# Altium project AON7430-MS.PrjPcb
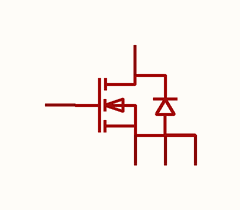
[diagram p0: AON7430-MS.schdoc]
1 sheet, 1 parts. Net scope: global (net labels, ports and power ports of the same name join across sheets).

## Sheet AON7430-MS.schdoc
size 127 x 101 mm

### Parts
Q?  aon7430-ms  [POWERDI3333-8_DMN7022LFGQ-7]  (value not drawn)

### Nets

Not connected (* = marked no-connect by the designer): Q? 1(S) 2(S) 3(S) 4(G) 5(D)

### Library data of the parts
Q? = aon7430-ms: 数量:1个N沟道;漏源电压(Vdss):30V;连续漏极电流(Id):30A;导通电阻(RDS(on)):20mΩ@4.5V;耗散功率(Pd):20W;阈值电压(Vgs(th)):2.5V;; Manufacturer: MSKSEMI(美森科); AddInBom: yes; ModelId: 296e462280334ba794f41fc0f4558c2c; ModelTransform: 130.708,130.708,0,0,0,0,0,18.625,0; Number: 1个N沟道; Drain to Source Voltage: 30V; Current - Continuous Drain(Id): 30A; Pd - Power Dissipation: 20W; Gate Threshold Voltage (Vgs(th)): 2.5V; Gate Charge(Qg): 2.2nC@4.5V,20V; Input Capacitance(Ciss): 572pF; Reverse Transfer Capacitance (Crss@Vds): 65pF; Output Capacitance(Coss): 81pF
